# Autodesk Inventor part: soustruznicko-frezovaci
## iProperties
Created: 2008-07
Part Number: soustruznicko-frezovaci
Document SubType Name: Modeling
Designer: Inteus
Density: 1 g/cm^3
Author: Inteus
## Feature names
1. Extrusion1
2. Extrusion3
3. Extrusion5
4. Extrusion6
5. Extrusion8
6. Extrusion9
7. Extrusion10
8. Extrusion11
9. Extrusion12
10. Chamfer2
11. Chamfer3
12. Fillet8
13. Fillet9
14. Extrusion14
15. Extrusion15
16. Extrusion16
17. Circular Pattern1
